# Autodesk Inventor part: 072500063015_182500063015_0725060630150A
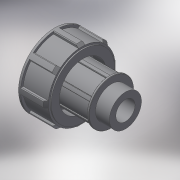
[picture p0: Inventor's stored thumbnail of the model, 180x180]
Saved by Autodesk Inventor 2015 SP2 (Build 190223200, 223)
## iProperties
Created: 2017-04
Part Number: 072500063015_182500063015_0725060630150A
Material: Generic
Description: PLASSON THREADED ADAPTOR 63-1.1/2"
Document SubType Name: Modeling
Designer: KIM
Density: 1 g/cm^3
Appearance: Default
Author: KIM
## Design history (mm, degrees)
derived "07250.ipt"
feature "Solid1::07250.ipt"
tag "TaggingFeature1"
body "Solid1"
other parameters: "d1" = 47.803, "d2" = 111, "d3" = 22, "d6" = 113, "d7" = 105.09, "d8" = 90.4, "d9" = 63, "d10" = 66.9242, "d12" = 28.6818, "d13" = 38.2424, "d14" = 25.3, "d15" = 84.75, "d16" = 3.33, "d17" = 44.4, "d18" = 22, "d19" = 26.4, "d24" = 9.5606, "d25" = 4.7803, "d27" = 0, "d28" = 3.82424, "d31" = 0.95606, "d35" = 360 deg, "d41" = 29.337, "d56" = 65.52, "d57" = 6.3, "d58" = 3.15, "d60" = 0, "d61" = 0.47803, "d64" = 0.47803, "d68" = 360 deg, "d_" = 63, "R_" = 47.803, "E_" = 113, "H_" = 111, "l_2" = 22, "d55" = 63
